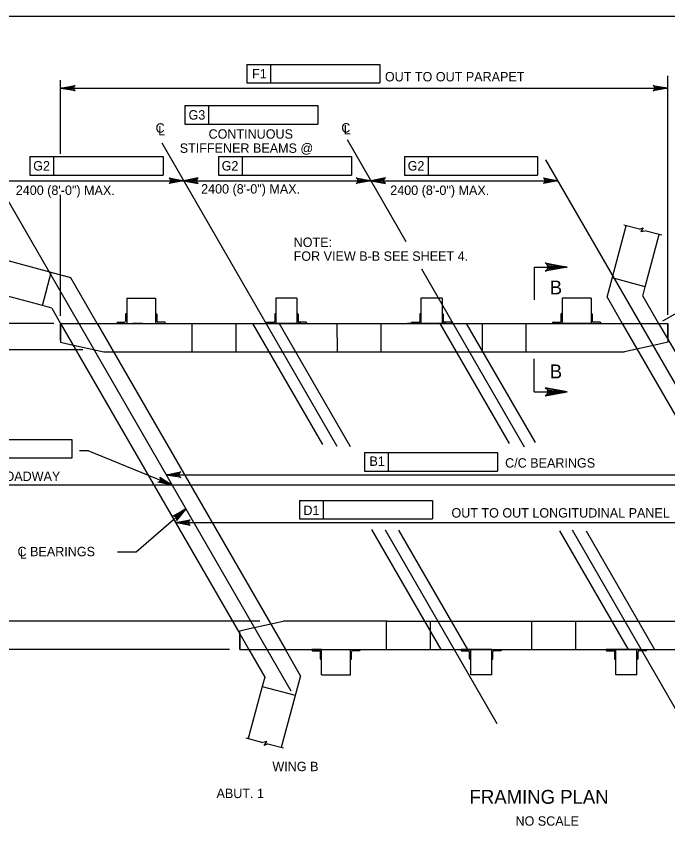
# Model space of a CAD drawing. Extents: x 638268 to 640277, y 295465 to 298435.
# Drawn here: x 639420.7 to 639628.9, y 296973.8 to 297232.5 of the extents above; entities that cross this region are included whole.
import ezdxf

# ---------------------------------------------------------------- set-up
doc = ezdxf.new("R2010")
doc.units = 0
for name, color, linetype in [('2', 7, 'Continuous'), ('3', 7, 'Continuous'), ('4', 7, 'Continuous')]:
    doc.layers.add(name, color=color, linetype=linetype)

msp = doc.modelspace()

# ---------------------------------------------------------------- linework, layer by layer
at = {"layer": '2'}
for p, q in [((639316.46, 297232.46), (640102.46, 297232.46)), ((639609.49, 297142.63), (639615.62, 297165.51)), ((639621.7, 297146.01), (639626.16, 297162.69)), ((639438.09, 297148.88), (639415.21, 297155.01)), ((639586.2, 297152.3), (639586.2, 297141.81)), ((639586.2, 297152.3), (639596.69, 297152.3)), ((639429.07, 297140), (639431.89, 297150.55)), ((639446.52, 297134.29), (639438.09, 297148.88)), ((639621.7, 297146.01), (639611.15, 297148.83)), ((639429.07, 297140), (639412.39, 297144.47)), ((639620.9, 297143.05), (639621.7, 297146.01)), ((639455.99, 297142.38), (639465.22, 297142.38)), ((639455.99, 297142.38), (639455.99, 297134.29)), ((639465.22, 297142.38), (639465.22, 297134.29)), ((639510.38, 297142.38), (639503.65, 297142.38)), ((639510.38, 297142.38), (639503.65, 297142.38)), ((639503.65, 297142.38), (639503.65, 297134.29)), ((639510.38, 297142.38), (639510.38, 297134.29)), ((639556.74, 297142.38), (639550.02, 297142.38)), ((639556.74, 297142.38), (639550.02, 297142.38)), ((639556.74, 297142.38), (639550.02, 297142.38)), ((639550.02, 297142.38), (639550.02, 297134.29)), ((639556.74, 297142.38), (639556.74, 297134.29)), ((639604.36, 297142.38), (639595.12, 297142.38)), ((639595.12, 297142.38), (639595.12, 297134.29)), ((639604.36, 297142.38), (639604.36, 297134.29)), ((639609.49, 297142.63), (639614.31, 297134.29)), ((639620.9, 297143.05), (639625.96, 297134.29)), ((639432.02, 297139.21), (639429.07, 297140)), ((639432.02, 297139.21), (639434.87, 297134.29)), ((639455.62, 297137.2), (639455.62, 297135.01)), ((639455.81, 297137.38), (639455.99, 297137.38)), ((639455.99, 297137.38), (639455.99, 297134.29)), ((639465.41, 297137.38), (639465.22, 297137.38)), ((639465.22, 297137.38), (639465.22, 297134.29)), ((639465.59, 297137.2), (639465.59, 297135.01)), ((639503.29, 297137.2), (639503.29, 297135.01)), ((639503.47, 297137.38), (639503.65, 297137.38)), ((639503.65, 297137.38), (639503.65, 297134.29)), ((639510.56, 297137.38), (639510.38, 297137.38)), ((639510.38, 297137.38), (639510.38, 297134.29)), ((639510.74, 297137.2), (639510.74, 297135.01)), ((639549.65, 297137.2), (639549.65, 297135.01)), ((639549.83, 297137.38), (639550.02, 297137.38)), ((639550.02, 297137.38), (639550.02, 297134.29)), ((639556.92, 297137.38), (639556.74, 297137.38)), ((639556.74, 297137.38), (639556.74, 297134.29)), ((639557.11, 297137.2), (639557.11, 297135.01)), ((639594.76, 297137.2), (639594.76, 297135.01)), ((639594.94, 297137.38), (639595.12, 297137.38)), ((639595.12, 297137.38), (639595.12, 297134.29)), ((639604.54, 297137.38), (639604.36, 297137.38)), ((639604.36, 297137.38), (639604.36, 297134.29)), ((639604.72, 297137.2), (639604.72, 297135.01)), ((639434.87, 297134.29), (639628.88, 297134.29)), ((639434.87, 297134.29), (639438.37, 297128.22)), ((639434.87, 297134.29), (639628.88, 297134.29)), ((639434.87, 297134.29), (639434.87, 297128.26)), ((639434.87, 297128.9), (639434.87, 297134.29)), ((639446.52, 297134.29), (639506.69, 297030.06)), ((639452.9, 297134.47), (639452.9, 297134.29)), ((639453.08, 297134.65), (639455.26, 297134.65)), ((639455.99, 297134.29), (639465.22, 297134.29)), ((639460.99, 297134.29), (639457.9, 297134.29)), ((639465.22, 297134.29), (639468.32, 297134.29)), ((639468.13, 297134.65), (639465.95, 297134.65)), ((639468.32, 297134.47), (639468.32, 297134.29)), ((639476.78, 297134.29), (639476.78, 297125.17)), ((639490.85, 297134.29), (639490.85, 297125.17)), ((639500.56, 297134.47), (639500.56, 297134.29)), ((639503.65, 297134.29), (639500.56, 297134.29)), ((639500.74, 297134.65), (639502.92, 297134.65)), ((639511.63, 297134.29), (639502.4, 297134.29)), ((639510.38, 297134.29), (639503.65, 297134.29)), ((639510.38, 297134.29), (639513.47, 297134.29)), ((639513.29, 297134.65), (639511.11, 297134.65)), ((639513.47, 297134.47), (639513.47, 297134.29)), ((639523.18, 297134.29), (639523.19, 297125.17)), ((639537.21, 297134.29), (639537.21, 297125.17)), ((639548.76, 297134.29), (639545.67, 297134.29)), ((639546.92, 297134.47), (639546.92, 297134.29)), ((639550.02, 297134.29), (639546.92, 297134.29)), ((639547.11, 297134.65), (639549.29, 297134.65)), ((639558, 297134.29), (639548.76, 297134.29)), ((639558, 297134.29), (639548.76, 297134.29)), ((639556.74, 297134.29), (639550.02, 297134.29)), ((639556.74, 297134.29), (639559.83, 297134.29)), ((639559.65, 297134.65), (639557.47, 297134.65)), ((639558, 297134.29), (639561.09, 297134.29)), ((639559.83, 297134.47), (639559.83, 297134.29)), ((639569.55, 297134.29), (639569.55, 297125.17)), ((639583.57, 297134.29), (639583.57, 297125.17)), ((639592.03, 297134.47), (639592.03, 297134.29)), ((639595.12, 297134.29), (639592.03, 297134.29)), ((639592.21, 297134.65), (639594.4, 297134.65)), ((639604.36, 297134.29), (639595.12, 297134.29)), ((639604.36, 297134.29), (639607.45, 297134.29)), ((639607.27, 297134.65), (639605.09, 297134.65)), ((639607.45, 297134.47), (639607.45, 297134.29)), ((639614.31, 297134.29), (639674.49, 297030.06)), ((639625.96, 297134.29), (639628.88, 297129.24)), ((639628.88, 297129.24), (639628.88, 297134.29)), ((639628.88, 297134.29), (639628.88, 297128.26)), ((639628.88, 297129.24), (639682.63, 297036.13)), ((639434.87, 297128.26), (639437.04, 297127.77)), ((639437.04, 297127.77), (639448.71, 297125.17)), ((639438.37, 297128.22), (639492.13, 297035.11)), ((639626.69, 297127.77), (639615.01, 297125.17)), ((639628.86, 297128.26), (639626.69, 297127.77)), ((639448.71, 297125.17), (639615.01, 297125.17)), ((639586.2, 297112.45), (639586.2, 297122.94)), ((639586.2, 297112.45), (639596.69, 297112.45)), ((639494.3, 297036.58), (639505.98, 297039.18)), ((639539.28, 297039.18), (639505.98, 297039.18)), ((639539.04, 297030.06), (639539.04, 297039.18)), ((639539.28, 297039.18), (639674.46, 297039.18)), ((639553.11, 297030.06), (639553.11, 297039.18)), ((639585.45, 297030.06), (639585.45, 297039.18)), ((639599.47, 297030.06), (639599.47, 297039.18)), ((639492.13, 297036.09), (639494.3, 297036.58)), ((639492.13, 297030.06), (639492.13, 297036.09)), ((639492.13, 297035.23), (639492.13, 297030.06)), ((639492.13, 297035.11), (639495.04, 297030.06)), ((639492.13, 297030.06), (639686.14, 297030.06)), ((639492.13, 297030.06), (639686.14, 297030.06)), ((639495.04, 297030.06), (639500.1, 297021.3)), ((639511.51, 297021.72), (639506.69, 297030.06)), ((639515.16, 297029.88), (639515.16, 297030.06)), ((639518.25, 297030.06), (639515.16, 297030.06)), ((639515.34, 297029.7), (639517.52, 297029.7)), ((639517.88, 297027.15), (639517.88, 297029.33)), ((639518.25, 297030.06), (639527.49, 297030.06)), ((639518.25, 297026.97), (639518.25, 297030.06)), ((639518.25, 297021.97), (639518.25, 297030.06)), ((639527.49, 297030.06), (639530.58, 297030.06)), ((639527.49, 297026.97), (639527.49, 297030.06)), ((639527.49, 297021.97), (639527.49, 297030.06)), ((639527.85, 297027.15), (639527.85, 297029.33)), ((639530.39, 297029.7), (639528.21, 297029.7)), ((639530.58, 297029.88), (639530.58, 297030.06)), ((639562.82, 297029.88), (639562.82, 297030.06)), ((639565.91, 297030.06), (639562.82, 297030.06)), ((639563, 297029.7), (639565.18, 297029.7)), ((639565.55, 297027.15), (639565.55, 297029.33)), ((639572.64, 297030.06), (639565.91, 297030.06)), ((639565.91, 297026.97), (639565.91, 297030.06)), ((639565.91, 297021.97), (639565.91, 297030.06)), ((639572.64, 297026.97), (639572.64, 297030.06)), ((639572.64, 297030.06), (639575.73, 297030.06)), ((639572.64, 297021.97), (639572.64, 297030.06)), ((639573, 297027.15), (639573, 297029.33)), ((639575.55, 297029.7), (639573.37, 297029.7)), ((639575.73, 297029.88), (639575.73, 297030.06)), ((639609.18, 297029.88), (639609.18, 297030.06)), ((639612.28, 297030.06), (639609.18, 297030.06)), ((639609.37, 297029.7), (639611.55, 297029.7)), ((639620.26, 297030.06), (639611.02, 297030.06)), ((639611.91, 297027.15), (639611.91, 297029.33)), ((639619, 297030.06), (639612.28, 297030.06)), ((639612.28, 297026.97), (639612.28, 297030.06)), ((639612.28, 297021.97), (639612.28, 297030.06)), ((639619, 297026.97), (639619, 297030.06)), ((639619, 297030.06), (639622.09, 297030.06)), ((639619, 297021.97), (639619, 297030.06)), ((639619.37, 297027.15), (639619.37, 297029.33)), ((639621.91, 297029.7), (639619.73, 297029.7)), ((639622.09, 297029.88), (639622.09, 297030.06)), ((639518.07, 297026.97), (639518.25, 297026.97)), ((639527.67, 297026.97), (639527.49, 297026.97)), ((639565.73, 297026.97), (639565.91, 297026.97)), ((639572.82, 297026.97), (639572.64, 297026.97)), ((639612.09, 297026.97), (639612.28, 297026.97)), ((639619.18, 297026.97), (639619, 297026.97)), ((639500.1, 297021.3), (639499.31, 297018.34)), ((639511.51, 297021.72), (639505.38, 296998.84)), ((639518.25, 297021.97), (639527.49, 297021.97)), ((639572.64, 297021.97), (639565.91, 297021.97)), ((639619, 297021.97), (639612.28, 297021.97)), ((639619, 297021.97), (639612.28, 297021.97)), ((639499.31, 297018.34), (639494.84, 297001.66)), ((639499.31, 297018.34), (639509.85, 297015.52))]:
    msp.add_line(p, q, dxfattribs=at)
for points in [[(639596.69, 297152.3), (639589.7, 297150.99), (639590.24, 297151.36), (639590.51, 297151.83), (639590.59, 297152.3), (639590.51, 297152.77), (639590.24, 297153.24), (639589.7, 297153.61), (639596.69, 297152.3), (639590.24, 297153.24), (639590.51, 297152.77), (639596.69, 297152.3), (639590.59, 297152.3), (639590.51, 297151.83), (639596.69, 297152.3), (639590.24, 297151.36)], [(639596.69, 297112.45), (639589.7, 297113.76), (639590.24, 297113.39), (639590.51, 297112.92), (639590.59, 297112.45), (639590.51, 297111.99), (639590.24, 297111.52), (639589.7, 297111.15), (639596.69, 297112.45), (639590.24, 297111.52), (639590.51, 297111.99), (639596.69, 297112.45), (639590.59, 297112.45), (639590.51, 297112.92), (639596.69, 297112.45), (639590.24, 297113.39)]]:
    msp.add_lwpolyline(points, dxfattribs=at)
for centre, radius, start, end in [((639455.81, 297137.2), 0.182, 90, 179.9984), ((639465.41, 297137.2), 0.182, 0.0016, 90), ((639503.47, 297137.2), 0.182, 90, 179.9984), ((639510.56, 297137.2), 0.182, 0.0016, 90), ((639549.83, 297137.2), 0.182, 90, 179.9984), ((639556.92, 297137.2), 0.182, 0.0016, 90), ((639594.94, 297137.2), 0.182, 90, 179.9984), ((639604.54, 297137.2), 0.182, 0.0016, 90), ((639453.08, 297134.47), 0.182, 90, 179.9984), ((639455.26, 297135.01), 0.364, 270, 359.9984), ((639465.95, 297135.01), 0.364, 180.0016, 270), ((639468.13, 297134.47), 0.182, 0.0016, 90), ((639500.74, 297134.47), 0.182, 90, 179.9984), ((639502.92, 297135.01), 0.364, 270, 359.9984), ((639511.11, 297135.01), 0.364, 180.0016, 270), ((639513.29, 297134.47), 0.182, 0.0016, 90), ((639547.11, 297134.47), 0.182, 90, 179.9984), ((639549.29, 297135.01), 0.364, 270, 359.9984), ((639557.47, 297135.01), 0.364, 180.0016, 270), ((639559.65, 297134.47), 0.182, 0.0016, 90), ((639592.21, 297134.47), 0.182, 90, 179.9984), ((639594.4, 297135.01), 0.364, 270, 359.9984), ((639605.09, 297135.01), 0.364, 180.0016, 270), ((639607.27, 297134.47), 0.182, 0.0016, 90), ((639515.34, 297029.88), 0.182, 180.0016, 270), ((639517.52, 297029.33), 0.364, 0.0016, 90), ((639528.21, 297029.33), 0.364, 90, 179.9984), ((639530.39, 297029.88), 0.182, 270, 359.9984), ((639563, 297029.88), 0.182, 180.0016, 270), ((639565.18, 297029.33), 0.364, 0.0016, 90), ((639573.37, 297029.33), 0.364, 90, 179.9984), ((639575.55, 297029.88), 0.182, 270, 359.9984), ((639609.37, 297029.88), 0.182, 180.0016, 270), ((639611.55, 297029.33), 0.364, 0.0016, 90), ((639619.73, 297029.33), 0.364, 90, 179.9984), ((639621.91, 297029.88), 0.182, 270, 359.9984), ((639518.07, 297027.15), 0.182, 180.0016, 270), ((639527.67, 297027.15), 0.182, 270, 359.9984), ((639565.73, 297027.15), 0.182, 180.0016, 270), ((639572.82, 297027.15), 0.182, 270, 359.9984), ((639612.09, 297027.15), 0.182, 180.0016, 270), ((639619.18, 297027.15), 0.182, 270, 359.9984)]:
    msp.add_arc(centre, radius, start, end, dxfattribs=at)
at = {"layer": '3'}
for p, q in [((639619.88, 297164.37), (639614.88, 297165.71)), ((639619.88, 297164.37), (639621.06, 297164.87)), ((639621.06, 297164.87), (639620.25, 297163.65)), ((639620.25, 297163.65), (639621.51, 297163.93)), ((639626.98, 297162.47), (639621.51, 297163.93)), ((639496.22, 297134.29), (639518.55, 297095.6)), ((639504.68, 297134.29), (639527.35, 297095.02)), ((639556.04, 297134.29), (639578.16, 297095.97)), ((639564.5, 297134.29), (639586.47, 297096.22)), ((639534.21, 297068.49), (639556.4, 297030.06)), ((639542.81, 297068.24), (639564.86, 297030.06)), ((639594.32, 297067.98), (639616.21, 297030.06)), ((639602.77, 297067.99), (639624.67, 297030.06)), ((639494.02, 297001.88), (639499.5, 297000.42)), ((639500.75, 297000.7), (639499.5, 297000.42)), ((639499.95, 296999.47), (639500.75, 297000.7)), ((639501.12, 296999.98), (639499.95, 296999.47)), ((639501.12, 296999.98), (639506.13, 296998.64))]:
    msp.add_line(p, q, dxfattribs=at)
at = {"layer": '4'}
for p, q in [((639494.33, 297217.02), (639536.85, 297217.02)), ((639494.33, 297217.02), (639494.33, 297211.12)), ((639501.89, 297217.02), (639501.89, 297211.12)), ((639536.85, 297217.02), (639536.85, 297211.12)), ((639434.87, 297188.47), (639434.87, 297211.99)), ((639628.88, 297137.07), (639628.88, 297213.37)), ((639434.87, 297209.44), (639628.88, 297209.44)), ((639494.33, 297211.12), (639536.85, 297211.12)), ((639474.59, 297203.87), (639517.11, 297203.87)), ((639474.59, 297203.87), (639474.59, 297197.97)), ((639482.15, 297203.87), (639482.15, 297197.97)), ((639517.11, 297203.87), (639517.11, 297197.97)), ((639474.59, 297197.97), (639517.11, 297197.97)), ((639467.19, 297192.03), (639523.11, 297095.04)), ((639526.39, 297193.1), (639545.21, 297160.45)), ((639425.09, 297187.61), (639467.61, 297187.61)), ((639425.09, 297187.61), (639425.09, 297181.7)), ((639432.65, 297187.61), (639432.65, 297181.7)), ((639467.61, 297187.61), (639467.61, 297181.7)), ((639485.29, 297187.61), (639527.81, 297187.61)), ((639485.29, 297187.61), (639485.29, 297181.7)), ((639492.85, 297187.61), (639492.85, 297181.7)), ((639527.81, 297187.61), (639527.81, 297181.7)), ((639544.73, 297187.61), (639587.25, 297187.61)), ((639544.73, 297187.61), (639544.73, 297181.7)), ((639552.29, 297187.61), (639552.29, 297181.7)), ((639587.25, 297187.61), (639587.25, 297181.7)), ((639688.63, 297015.66), (639589.95, 297186.58)), ((639508.5, 297016.85), (639411.4, 297185.03)), ((639425.09, 297181.7), (639467.61, 297181.7)), ((639485.29, 297181.7), (639527.81, 297181.7)), ((639544.73, 297181.7), (639587.25, 297181.7)), ((639627.32, 297135.07), (639707.53, 297181.38)), ((639414.36, 297179.9), (639593.8, 297179.9)), ((639434.87, 297136.69), (639434.87, 297175.34)), ((639550.24, 297151.72), (639583.01, 297094.89)), ((639432.73, 297134.29), (639336.8, 297134.29)), ((639442, 297125.83), (639376.05, 297125.83)), ((639395.98, 297097.16), (639438.5, 297097.16)), ((639438.5, 297097.16), (639438.5, 297091.26)), ((639443.71, 297093.63), (639440.95, 297093.63)), ((639443.78, 297093.63), (639440.95, 297093.63)), ((639470.55, 297082.58), (639443.71, 297093.63)), ((639531.94, 297093.01), (639574.46, 297093.01)), ((639531.94, 297093.01), (639531.94, 297087.11)), ((639539.5, 297093.01), (639539.5, 297087.11)), ((639574.46, 297093.01), (639574.46, 297087.11)), ((639438.5, 297091.26), (639395.98, 297091.26)), ((639468.6, 297085.95), (639648.04, 297085.95)), ((639531.94, 297087.11), (639574.46, 297087.11)), ((639707.69, 297082.58), (639405.47, 297082.58)), ((639511.19, 297077.75), (639553.71, 297077.75)), ((639511.19, 297077.75), (639511.19, 297071.85)), ((639518.75, 297077.75), (639518.75, 297071.85)), ((639553.71, 297077.75), (639553.71, 297071.85)), ((639459.03, 297061.32), (639474.87, 297075.1)), ((639511.19, 297071.85), (639553.71, 297071.85)), ((639471.61, 297070.65), (639662.7, 297070.65)), ((639538.53, 297068.34), (639574.21, 297006.52)), ((639598.34, 297068.34), (639634.03, 297006.52)), ((639453.05, 297061.32), (639459.03, 297061.32)), ((639498.57, 297039.18), (639376.05, 297039.18)), ((639488.89, 297030.06), (639336.8, 297030.06))]:
    msp.add_line(p, q, dxfattribs=at)
for points in [[(639434.87, 297209.44), (639439.53, 297210.31), (639439.17, 297210.06), (639438.98, 297209.75), (639438.93, 297209.44), (639438.98, 297209.13), (639439.17, 297208.81), (639439.53, 297208.57), (639434.87, 297209.44), (639439.17, 297208.81), (639438.98, 297209.13), (639434.87, 297209.44), (639438.93, 297209.44), (639438.98, 297209.75), (639434.87, 297209.44), (639439.17, 297210.06)], [(639628.88, 297209.44), (639624.22, 297208.57), (639624.58, 297208.81), (639624.76, 297209.13), (639624.82, 297209.44), (639624.76, 297209.75), (639624.58, 297210.06), (639624.22, 297210.31), (639628.88, 297209.44), (639624.58, 297210.06), (639624.76, 297209.75), (639628.88, 297209.44), (639624.82, 297209.44), (639624.76, 297209.13), (639628.88, 297209.44), (639624.58, 297208.81)], [(639474.19, 297179.9), (639469.53, 297179.02), (639469.88, 297179.27), (639470.07, 297179.59), (639470.12, 297179.9), (639470.07, 297180.21), (639469.88, 297180.52), (639469.53, 297180.77), (639474.19, 297179.9), (639469.88, 297180.52), (639470.07, 297180.21), (639474.19, 297179.9), (639470.12, 297179.9), (639470.07, 297179.59), (639474.19, 297179.9), (639469.88, 297179.27)], [(639474.19, 297179.9), (639478.85, 297179.02), (639478.49, 297179.27), (639478.3, 297179.59), (639478.25, 297179.9), (639478.3, 297180.21), (639478.49, 297180.52), (639478.85, 297180.77), (639474.19, 297179.9), (639478.49, 297180.52), (639478.3, 297180.21), (639474.19, 297179.9), (639478.25, 297179.9), (639478.3, 297179.59), (639474.19, 297179.9), (639478.49, 297179.27)], [(639534, 297179.9), (639529.34, 297179.02), (639529.7, 297179.27), (639529.88, 297179.59), (639529.94, 297179.9), (639529.88, 297180.21), (639529.7, 297180.52), (639529.34, 297180.77), (639534, 297179.9), (639529.7, 297180.52), (639529.88, 297180.21), (639534, 297179.9), (639529.94, 297179.9), (639529.88, 297179.59), (639534, 297179.9), (639529.7, 297179.27)], [(639534, 297179.9), (639538.66, 297179.02), (639538.3, 297179.27), (639538.12, 297179.59), (639538.06, 297179.9), (639538.12, 297180.21), (639538.3, 297180.52), (639538.66, 297180.77), (639534, 297179.9), (639538.3, 297180.52), (639538.12, 297180.21), (639534, 297179.9), (639538.06, 297179.9), (639538.12, 297179.59), (639534, 297179.9), (639538.3, 297179.27)], [(639593.8, 297179.9), (639589.14, 297179.02), (639589.5, 297179.27), (639589.69, 297179.59), (639589.74, 297179.9), (639589.69, 297180.21), (639589.5, 297180.52), (639589.14, 297180.77), (639593.8, 297179.9), (639589.5, 297180.52), (639589.69, 297180.21), (639593.8, 297179.9), (639589.74, 297179.9), (639589.69, 297179.59), (639593.8, 297179.9), (639589.5, 297179.27)], [(639470.55, 297082.58), (639465.91, 297083.55), (639466.33, 297083.64), (639466.62, 297083.86), (639466.79, 297084.13), (639466.86, 297084.44), (639466.81, 297084.8), (639466.57, 297085.16), (639470.55, 297082.58), (639466.81, 297084.8), (639466.86, 297084.44), (639470.55, 297082.58), (639466.79, 297084.13), (639466.62, 297083.86), (639470.55, 297082.58), (639466.33, 297083.64)], [(639468.6, 297085.95), (639473.26, 297086.83), (639472.9, 297086.58), (639472.72, 297086.27), (639472.66, 297085.95), (639472.72, 297085.64), (639472.9, 297085.33), (639473.26, 297085.08), (639468.6, 297085.95), (639472.9, 297085.33), (639472.72, 297085.64), (639468.6, 297085.95), (639472.66, 297085.95), (639472.72, 297086.27), (639468.6, 297085.95), (639472.9, 297086.58)], [(639474.87, 297075.1), (639471.92, 297071.38), (639472.03, 297071.8), (639471.97, 297072.16), (639471.8, 297072.43), (639471.56, 297072.63), (639471.21, 297072.75), (639470.78, 297072.7), (639474.87, 297075.1), (639471.21, 297072.75), (639471.56, 297072.63), (639474.87, 297075.1), (639471.8, 297072.43), (639471.97, 297072.16), (639474.87, 297075.1), (639472.03, 297071.8)], [(639471.61, 297070.65), (639476.27, 297071.52), (639475.91, 297071.28), (639475.72, 297070.96), (639475.67, 297070.65), (639475.72, 297070.34), (639475.91, 297070.03), (639476.27, 297069.78), (639471.61, 297070.65), (639475.91, 297070.03), (639475.72, 297070.34), (639471.61, 297070.65), (639475.67, 297070.65), (639475.72, 297070.96), (639471.61, 297070.65), (639475.91, 297071.28)]]:
    msp.add_lwpolyline(points, dxfattribs=at)
msp.add_lwpolyline([(639467.81, 297083.21), (639468.16, 297084.06), (639470.55, 297082.58)], close=True, dxfattribs=at)

# ---------------------------------------------------------------- texts
for s, height, rotation, p in [('F1', 3, 359.9382, (639496.05, 297212.57)), ('G3', 3, 359.9382, (639475.75, 297199.42)), ('G2', 3, 359.9382, (639426.12, 297183.15)), ('G2', 3, 359.9382, (639486.33, 297183.15)), ('G2', 3, 359.9382, (639545.76, 297183.15)), ('2400 (8\'-0") MAX.', 3, 359.9382, (639420.56, 297175.36)), ('2400 (8\'-0") MAX.', 3, 359.9382, (639479.77, 297175.79)), ('2400 (8\'-0") MAX.', 3, 359.9382, (639540.2, 297175.36)), ('B', 4.43, 360, (639591.15, 297143.57)), ('B', 4.43, 360, (639591.15, 297116.75)), ('B1', 3, 359.9382, (639533.56, 297088.79)), ('D1', 3, 359.9382, (639512.45, 297073.07))]:
    msp.add_text(s, height=height, rotation=rotation, dxfattribs=at).set_placement(p)
for s, height, p in [('OUT TO OUT PARAPET ', 3, (639538.5, 297211.62)), ('C', 3, (639465.22, 297195.24)), ('L', 3, (639466.05, 297194.35)), ('CONTINUOUS', 3, (639482.15, 297193.32)), ('C', 3, (639524.56, 297195.29)), ('L', 3, (639525.35, 297194.71)), ('STIFFENER BEAMS @', 3, (639472.94, 297188.8)), ('NOTE:', 3, (639509.34, 297158.74)), ('FOR VIEW B-B SEE SHEET 4.', 3, (639509.34, 297154.3)), ('C/C BEARINGS', 3, (639576.91, 297088.23)), ('L ROADWAY', 3, (639410.7, 297083.96)), ('OUT TO OUT LONGITUDINAL PANEL', 3, (639559.76, 297072.27)), ('C BEARINGS', 3, (639421.11, 297059.91)), ('L', 3, (639421.85, 297059.13)), ('WING B', 3, (639502.55, 296991.23)), ('ABUT. 1', 3, (639484.69, 296982.64)), ('FRAMING PLAN', 4.4292, (639565.55, 296980.81)), ('NO SCALE', 3, (639580.22, 296973.82))]:
    msp.add_text(s, height=height, dxfattribs=at).set_placement(p)

doc.saveas('drawing.dxf')
